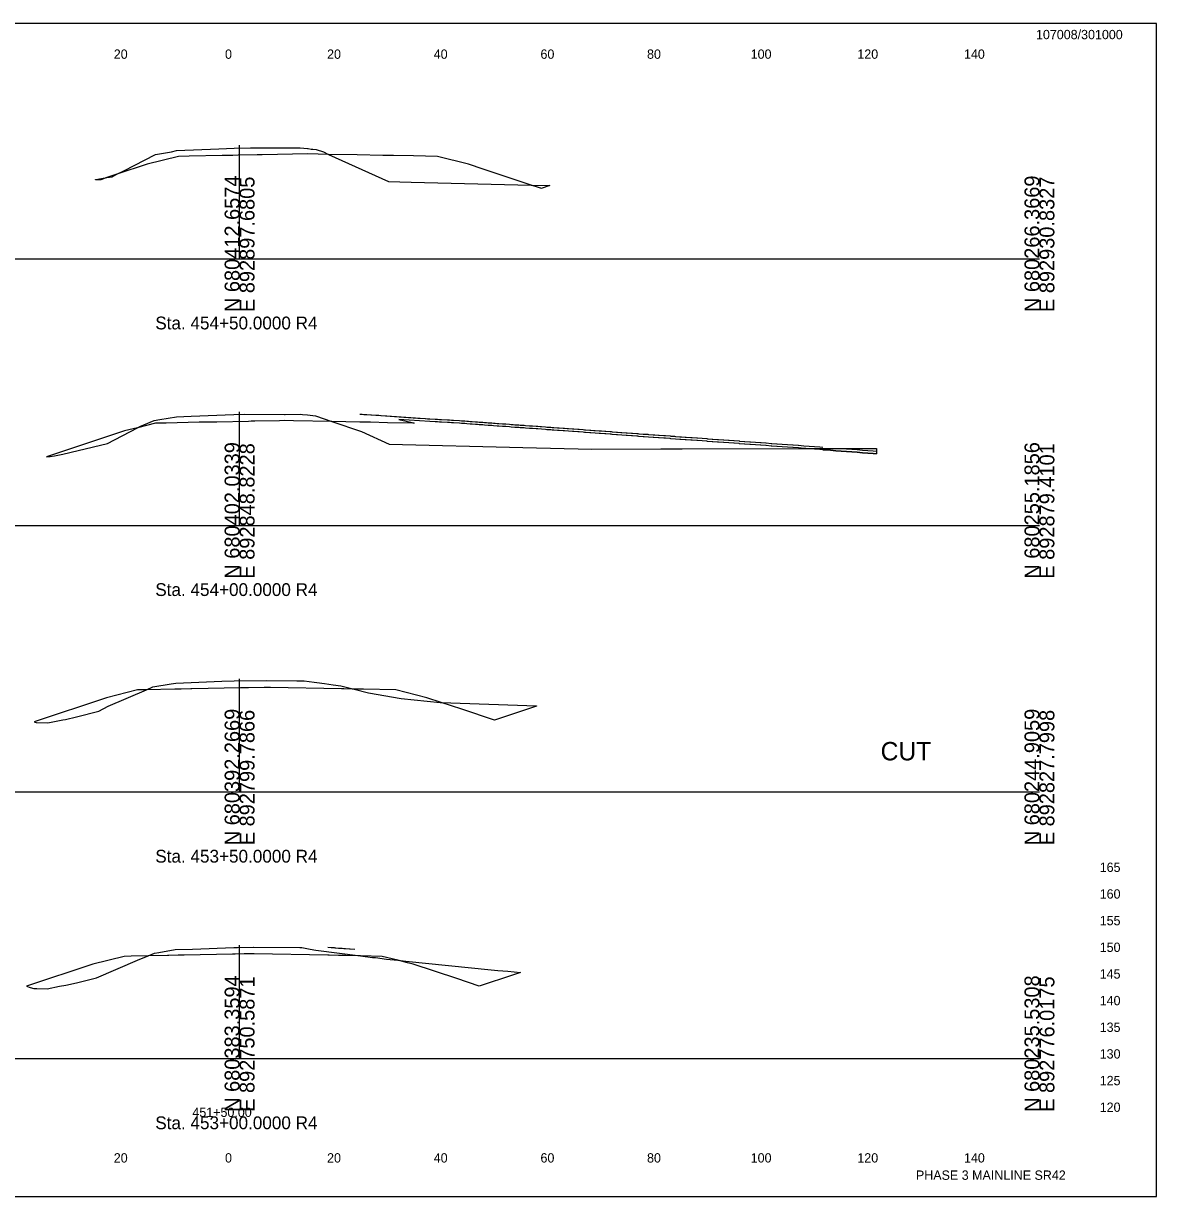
# Model space of a CAD drawing. Extents: x 21059 to 22955, y 6470 to 17494.
# Drawn here: x 21604.3 to 21816.8, y 7159 to 7379 of the extents above; entities that cross this region are included whole.
import ezdxf

# ---------------------------------------------------------------- set-up
doc = ezdxf.new("R2010")
doc.units = 0
for name, color, linetype in [('CONST_DCH', 7, 'Continuous'), ('Draft_XS_Grid', 7, 'Continuous'), ('Draft_XS_Text', 7, 'Continuous'), ('DTM CONTOURS_MAJOR', 7, 'Continuous'), ('DTM_TEMP_DROP', 7, 'Continuous'), ('SLOPE_STAKES_FILL', 7, 'Continuous'), ('X_PROFILES_1', 7, 'Continuous'), ('XS_M_SHAPES_EARTHWORK', 7, 'Continuous'), ('XS_P_TX_CLEARZONE', 7, 'Continuous'), ('XS_SHEET_EW_TX_VOLUME', 7, 'Continuous'), ('XS_X_SHOULDER', 7, 'Continuous')]:
    doc.layers.add(name, color=color, linetype=linetype)

msp = doc.modelspace()

# ---------------------------------------------------------------- linework, layer by layer
at = {"layer": 'DTM CONTOURS_MAJOR'}
for p, q in [((21644.84, 7334.84), (21644.84, 7356.12)), ((21494.84, 7334.84), (21644.84, 7334.84)), ((21644.84, 7334.84), (21794.84, 7334.84)), ((21644.84, 7284.84), (21644.84, 7306.1)), ((21494.84, 7284.84), (21644.84, 7284.84)), ((21644.84, 7284.84), (21794.84, 7284.84)), ((21644.84, 7234.84), (21644.84, 7256.08)), ((21494.84, 7234.84), (21644.84, 7234.84)), ((21644.84, 7234.84), (21794.84, 7234.84)), ((21644.84, 7184.84), (21644.84, 7206.12)), ((21494.84, 7184.84), (21644.84, 7184.84)), ((21644.84, 7184.84), (21794.84, 7184.84))]:
    msp.add_line(p, q, dxfattribs=at)
at = {"layer": 'DTM_TEMP_DROP'}
msp.add_lwpolyline([(21470.8, 7158.96), (21816.8, 7158.96), (21816.8, 7378.96), (21470.8, 7378.96)], close=True, dxfattribs=at)
at = {"layer": 'XS_M_SHAPES_EARTHWORK'}
for points in [[(21667.38, 7305.7), (21668.13, 7305.64), (21668.48, 7305.61), (21671.4, 7305.43)], [(21670.55, 7305.57), (21670.56, 7305.57), (21670.57, 7305.57), (21670.61, 7305.57), (21671.4, 7305.43), (21672.31, 7305.37), (21672.44, 7305.37), (21680.52, 7304.82), (21681.54, 7304.74), (21681.94, 7304.73), (21682.33, 7304.71), (21682.72, 7304.69), (21683.84, 7304.62), (21684.21, 7304.6), (21684.58, 7304.58), (21684.94, 7304.55), (21686.09, 7304.48), (21686.44, 7304.45), (21687.1, 7304.41), (21687.44, 7304.38), (21688.11, 7304.33), (21688.45, 7304.31), (21689.11, 7304.26), (21689.45, 7304.24), (21689.78, 7304.21), (21690.45, 7304.16), (21690.78, 7304.14), (21691.46, 7304.09), (21692.14, 7304.04), (21692.46, 7304.02), (21693.15, 7303.97), (21693.46, 7303.94), (21694.16, 7303.89), (21694.46, 7303.87), (21694.77, 7303.85), (21695.47, 7303.8), (21695.77, 7303.77), (21696.47, 7303.72), (21697.18, 7303.67), (21697.47, 7303.65), (21698.19, 7303.6), (21698.48, 7303.58), (21699.2, 7303.52), (21699.48, 7303.5), (21699.76, 7303.48), (21700.48, 7303.43), (21700.76, 7303.41), (21701.49, 7303.36), (21702.22, 7303.3), (21702.49, 7303.28), (21703.23, 7303.23), (21703.49, 7303.21), (21703.75, 7303.19), (21704.49, 7303.14), (21704.75, 7303.12), (21705.5, 7303.07), (21705.75, 7303.05), (21706.5, 7302.99), (21707.26, 7302.94), (21707.5, 7302.92), (21708.27, 7302.86), (21708.51, 7302.85), (21709.28, 7302.79), (21709.51, 7302.77), (21709.74, 7302.76), (21710.51, 7302.7), (21710.74, 7302.68), (21711.51, 7302.63), (21712.3, 7302.57), (21712.52, 7302.55), (21713.31, 7302.5), (21713.52, 7302.48), (21714.32, 7302.42), (21714.52, 7302.41), (21714.73, 7302.39), (21715.53, 7302.33), (21715.73, 7302.32), (21716.53, 7302.26), (21717.34, 7302.2), (21717.53, 7302.19), (21718.35, 7302.13), (21718.54, 7302.12), (21719.36, 7302.06), (21719.54, 7302.04), (21719.72, 7302.03), (21720.54, 7301.97), (21720.71, 7301.96), (21721.54, 7301.9), (21722.38, 7301.84), (21722.55, 7301.82), (21723.39, 7301.76), (21723.55, 7301.75), (21724.4, 7301.69), (21724.55, 7301.68), (21724.71, 7301.67), (21725.56, 7301.6), (21725.7, 7301.59), (21726.56, 7301.53), (21727.42, 7301.47), (21727.56, 7301.46), (21728.43, 7301.39), (21728.57, 7301.38), (21729.44, 7301.32), (21729.57, 7301.31), (21729.69, 7301.3), (21730.57, 7301.24), (21730.69, 7301.23), (21731.57, 7301.17), (21732.47, 7301.1), (21732.58, 7301.09), (21733.47, 7301.03), (21733.58, 7301.02), (21734.48, 7300.95), (21734.58, 7300.95), (21734.68, 7300.94), (21735.59, 7300.87), (21735.68, 7300.87), (21736.59, 7300.8), (21737.51, 7300.73), (21737.59, 7300.73), (21738.51, 7300.66), (21738.6, 7300.65), (21739.52, 7300.59), (21739.6, 7300.58), (21740.53, 7300.51), (21740.6, 7300.51), (21740.67, 7300.5), (21741.6, 7300.43), (21742.55, 7300.37), (21742.61, 7300.36), (21743.56, 7300.29), (21743.61, 7300.29), (21744.56, 7300.22), (21744.61, 7300.22), (21744.66, 7300.21), (21745.62, 7300.14), (21745.66, 7300.14), (21746.62, 7300.07), (21747.59, 7300), (21747.62, 7300), (21748.6, 7299.92), (21748.63, 7299.92), (21748.65, 7299.92), (21749.63, 7299.85), (21749.65, 7299.85), (21750.63, 7299.78), (21750.65, 7299.78), (21751.63, 7299.7), (21752.63, 7299.63), (21752.64, 7299.63), (21753.64, 7299.56), (21753.64, 7299.56), (21754.22, 7299.52)], [(21661.38, 7205.72), (21662, 7205.67), (21662.75, 7205.62)], [(21662.02, 7205.69), (21662.04, 7205.69), (21662.06, 7205.69), (21662.18, 7205.68), (21662.2, 7205.68), (21662.3, 7205.68), (21662.41, 7205.67), (21662.46, 7205.65), (21662.57, 7205.64), (21662.6, 7205.64), (21662.69, 7205.63), (21662.75, 7205.62), (21663.38, 7205.57), (21663.39, 7205.57), (21663.98, 7205.53), (21664.07, 7205.53), (21664.4, 7205.51), (21666.45, 7205.35)]]:
    msp.add_lwpolyline(points, dxfattribs=at)
at = {"layer": 'XS_P_TX_CLEARZONE'}
for points in [[(21667.38, 7305.7), (21667.79, 7305.68), (21667.84, 7305.68), (21678.27, 7304.94), (21678.72, 7304.92), (21679.68, 7304.85), (21680.1, 7304.83), (21680.52, 7304.82), (21681.54, 7304.74), (21681.94, 7304.73), (21682.33, 7304.71), (21682.72, 7304.69), (21683.84, 7304.62), (21684.21, 7304.6), (21684.58, 7304.58), (21684.94, 7304.55), (21686.09, 7304.48), (21686.44, 7304.45), (21686.79, 7304.43), (21687.44, 7304.38), (21687.79, 7304.36), (21688.45, 7304.31), (21689.11, 7304.26), (21689.45, 7304.24), (21689.78, 7304.21), (21690.45, 7304.16), (21691.13, 7304.11), (21691.46, 7304.09), (21692.14, 7304.04), (21692.46, 7304.02), (21692.77, 7303.99), (21693.46, 7303.94), (21694.16, 7303.89), (21694.46, 7303.87), (21694.77, 7303.85), (21695.47, 7303.8), (21696.17, 7303.75), (21696.47, 7303.72), (21697.18, 7303.67), (21697.47, 7303.65), (21698.19, 7303.6), (21698.48, 7303.58), (21699.2, 7303.52), (21699.48, 7303.5), (21699.76, 7303.48), (21700.48, 7303.43), (21701.21, 7303.38), (21701.49, 7303.36), (21702.22, 7303.3), (21702.49, 7303.28), (21702.75, 7303.27), (21703.49, 7303.21), (21703.75, 7303.19), (21704.49, 7303.14), (21704.75, 7303.12), (21705.5, 7303.07), (21706.25, 7303.01), (21706.5, 7302.99), (21707.26, 7302.94), (21707.5, 7302.92), (21708.27, 7302.86), (21708.51, 7302.85), (21709.28, 7302.79), (21709.51, 7302.77), (21709.74, 7302.76), (21710.51, 7302.7), (21711.29, 7302.64), (21711.51, 7302.63), (21712.3, 7302.57), (21712.52, 7302.55), (21712.73, 7302.54), (21713.52, 7302.48), (21714.32, 7302.42), (21714.52, 7302.41), (21714.73, 7302.39), (21715.53, 7302.33), (21716.33, 7302.28), (21716.53, 7302.26), (21717.34, 7302.2), (21717.53, 7302.19), (21718.35, 7302.13), (21718.54, 7302.12), (21719.36, 7302.06), (21719.54, 7302.04), (21719.72, 7302.03), (21720.54, 7301.97), (21721.38, 7301.91), (21721.54, 7301.9), (21722.38, 7301.84), (21722.55, 7301.82), (21722.71, 7301.81), (21723.55, 7301.75), (21724.4, 7301.69), (21724.55, 7301.68), (21724.71, 7301.67), (21725.56, 7301.6), (21726.42, 7301.54), (21726.56, 7301.53), (21727.42, 7301.47), (21727.56, 7301.46), (21727.7, 7301.45), (21728.57, 7301.38), (21729.44, 7301.32), (21729.57, 7301.31), (21729.69, 7301.3), (21730.57, 7301.24), (21730.69, 7301.23), (21731.57, 7301.17), (21732.47, 7301.1), (21732.58, 7301.09), (21732.69, 7301.08), (21733.58, 7301.02), (21734.48, 7300.95), (21734.58, 7300.95), (21734.68, 7300.94), (21735.59, 7300.87), (21736.5, 7300.81), (21736.59, 7300.8), (21736.68, 7300.79), (21737.59, 7300.73), (21738.51, 7300.66), (21738.6, 7300.65), (21739.52, 7300.59), (21739.6, 7300.58), (21740.53, 7300.51), (21740.6, 7300.51), (21740.67, 7300.5), (21741.6, 7300.43), (21742.55, 7300.37), (21742.61, 7300.36), (21742.67, 7300.36), (21743.61, 7300.29), (21744.56, 7300.22), (21744.61, 7300.22), (21744.66, 7300.21), (21745.62, 7300.14), (21745.66, 7300.14), (21746.62, 7300.07), (21747.59, 7300), (21747.62, 7300), (21748.6, 7299.92), (21748.63, 7299.92), (21749.6, 7299.85), (21749.63, 7299.85), (21749.65, 7299.85), (21750.63, 7299.78), (21750.65, 7299.78), (21751.63, 7299.7), (21752.63, 7299.63), (21752.64, 7299.63), (21752.64, 7299.63), (21753.64, 7299.56), (21754.22, 7299.52)], [(21661.38, 7205.72), (21662, 7205.67), (21666.45, 7205.35)]]:
    msp.add_lwpolyline(points, dxfattribs=at)
at = {"layer": 'XS_SHEET_EW_TX_VOLUME'}
for points in [[(21621.83, 7350.67), (21623.14, 7351.33), (21629.06, 7354.42), (21632.1, 7354.89), (21633, 7355.11), (21640.97, 7355.48), (21643.8, 7355.6), (21646.86, 7355.63), (21656.16, 7355.66), (21656.19, 7355.62), (21657.55, 7355.51), (21657.73, 7355.49), (21658.26, 7355.42), (21658.57, 7355.41), (21659.23, 7355.32), (21660.59, 7354.86), (21661.54, 7354.42), (21657.66, 7354.5), (21649.1, 7354.33), (21648.75, 7354.32), (21648.14, 7354.31), (21644.55, 7354.24), (21643.6, 7354.22), (21641.83, 7354.19), (21641.59, 7354.18), (21635.36, 7354.06), (21633.38, 7354.02), (21627.53, 7352.56)], [(21661.54, 7354.42), (21672.74, 7349.31), (21677.02, 7349.21), (21699.53, 7348.66), (21690.55, 7351.65), (21687.79, 7352.56), (21681.94, 7354.02), (21677.46, 7354.11), (21673.73, 7354.18), (21672.82, 7354.2), (21671.72, 7354.22), (21666.91, 7354.32)], [(21619.95, 7350.05), (21620.94, 7350.22), (21621.83, 7350.67)], [(21617.85, 7349.64), (21617.85, 7349.67), (21617.88, 7349.68), (21619.95, 7350.05), (21618.8, 7349.66), (21618.41, 7349.65)], [(21699.53, 7348.66), (21703.05, 7348.58), (21701.42, 7348.04), (21701.35, 7348.06), (21701.09, 7348.15)], [(21625.71, 7303.15), (21626.11, 7303.36), (21628.81, 7304.51), (21629.91, 7304.7), (21632.98, 7305.18), (21635.79, 7305.3), (21643.78, 7305.66), (21645.79, 7305.67), (21653.24, 7305.65), (21653.36, 7305.65), (21656.33, 7305.68), (21656.61, 7305.66), (21657.57, 7305.56), (21659.05, 7305.36), (21662.16, 7304.3), (21654.95, 7304.45), (21653.34, 7304.48), (21652.32, 7304.46), (21647.67, 7304.36), (21647.02, 7304.35), (21646.49, 7304.34), (21640.58, 7304.22), (21639.3, 7304.2), (21637.57, 7304.16), (21637.29, 7304.16), (21631.05, 7304.03), (21629.1, 7303.99)], [(21662.16, 7304.3), (21667.71, 7302.42), (21672.89, 7300.06), (21697.93, 7299.44), (21710.93, 7299.13), (21723.85, 7299.21), (21727.83, 7299.2), (21750.08, 7299.25), (21751.01, 7299.25), (21750.65, 7299.28), (21750.63, 7299.28), (21749.65, 7299.35), (21749.63, 7299.35), (21748.65, 7299.42), (21748.63, 7299.42), (21748.6, 7299.42), (21747.62, 7299.5), (21747.59, 7299.5), (21746.62, 7299.57), (21745.66, 7299.64), (21745.62, 7299.64), (21744.66, 7299.71), (21744.61, 7299.72), (21744.56, 7299.72), (21743.61, 7299.79), (21743.56, 7299.79), (21742.61, 7299.86), (21742.55, 7299.87), (21741.6, 7299.93), (21740.67, 7300), (21740.6, 7300.01), (21740.53, 7300.01), (21739.6, 7300.08), (21739.52, 7300.09), (21738.6, 7300.15), (21738.51, 7300.16), (21737.59, 7300.23), (21737.51, 7300.23), (21736.59, 7300.3), (21735.68, 7300.37), (21735.59, 7300.37), (21734.68, 7300.44), (21734.58, 7300.45), (21734.48, 7300.45), (21733.58, 7300.52), (21733.47, 7300.53), (21732.58, 7300.59), (21732.47, 7300.6), (21731.57, 7300.67), (21730.69, 7300.73), (21730.57, 7300.74), (21729.69, 7300.8), (21729.57, 7300.81), (21729.44, 7300.82), (21728.57, 7300.88), (21728.43, 7300.89), (21727.56, 7300.96), (21727.42, 7300.97), (21726.56, 7301.03), (21725.7, 7301.09), (21725.56, 7301.1), (21724.71, 7301.17), (21724.55, 7301.18), (21724.4, 7301.19), (21723.55, 7301.25), (21723.39, 7301.26), (21722.55, 7301.32), (21722.38, 7301.34), (21721.54, 7301.4), (21720.71, 7301.46), (21720.54, 7301.47), (21719.72, 7301.53), (21719.54, 7301.54), (21719.36, 7301.56), (21718.54, 7301.62), (21718.35, 7301.63), (21717.53, 7301.69), (21717.34, 7301.7), (21716.53, 7301.76), (21715.73, 7301.82), (21715.53, 7301.83), (21714.73, 7301.89), (21714.52, 7301.91), (21714.32, 7301.92), (21713.52, 7301.98), (21713.31, 7302), (21712.52, 7302.05), (21712.3, 7302.07), (21711.51, 7302.13), (21710.74, 7302.18), (21710.51, 7302.2), (21709.74, 7302.26), (21709.51, 7302.27), (21709.28, 7302.29), (21708.51, 7302.35), (21708.27, 7302.36), (21707.5, 7302.42), (21707.26, 7302.44), (21706.5, 7302.49), (21705.75, 7302.55), (21705.5, 7302.57), (21704.75, 7302.62), (21704.49, 7302.64), (21703.75, 7302.69), (21703.49, 7302.71), (21703.23, 7302.73), (21702.49, 7302.78), (21702.22, 7302.8), (21701.49, 7302.86), (21700.76, 7302.91), (21700.48, 7302.93), (21699.76, 7302.98), (21699.48, 7303), (21699.2, 7303.02), (21698.48, 7303.08), (21698.19, 7303.1), (21697.47, 7303.15), (21697.18, 7303.17), (21696.47, 7303.22), (21695.77, 7303.27), (21695.47, 7303.3), (21694.77, 7303.35), (21694.46, 7303.37), (21694.16, 7303.39), (21693.46, 7303.44), (21693.15, 7303.47), (21692.46, 7303.52), (21692.14, 7303.54), (21691.46, 7303.59), (21690.78, 7303.64), (21690.45, 7303.66), (21689.78, 7303.71), (21689.45, 7303.74), (21689.11, 7303.76), (21688.45, 7303.81), (21688.11, 7303.83), (21687.44, 7303.88), (21687.1, 7303.91), (21686.44, 7303.95), (21686.09, 7303.98), (21684.94, 7304.05), (21684.58, 7304.08), (21684.21, 7304.1), (21683.84, 7304.12), (21682.72, 7304.19), (21682.33, 7304.21), (21681.94, 7304.23), (21681.54, 7304.24), (21680.52, 7304.32), (21674.71, 7304.71), (21676.92, 7304.16), (21677.59, 7304), (21672.59, 7304.09), (21669.39, 7304.16), (21668.02, 7304.19), (21667.38, 7304.2)], [(21608.63, 7297.68), (21609.33, 7297.73), (21610.16, 7297.9), (21611.69, 7298.18), (21618.73, 7299.86), (21620.08, 7300.21), (21625.71, 7303.15), (21623.25, 7302.54)], [(21751.01, 7299.25), (21764.29, 7299.28), (21764.29, 7298.28), (21763.67, 7298.33), (21762.67, 7298.4), (21761.66, 7298.47), (21760.66, 7298.55), (21759.66, 7298.62), (21758.65, 7298.69), (21757.65, 7298.77), (21756.65, 7298.84), (21755.65, 7298.91), (21754.64, 7298.98), (21754.22, 7299.02), (21753.64, 7299.06), (21753.64, 7299.06), (21752.64, 7299.13), (21752.63, 7299.13), (21751.63, 7299.2)], [(21757.68, 7299.27), (21764.29, 7299.28), (21764.29, 7298.68), (21763.67, 7298.73), (21762.67, 7298.82), (21761.66, 7298.9), (21760.66, 7298.98), (21759.66, 7299.07), (21758.65, 7299.15), (21757.69, 7299.22)], [(21627.38, 7254.01), (21628.59, 7254.53), (21631.98, 7255.11), (21632.89, 7255.25), (21641.49, 7255.61), (21643.83, 7255.71), (21649.9, 7255.75), (21649.91, 7255.75), (21655.58, 7255.69), (21656.47, 7255.7), (21656.97, 7255.66), (21658.8, 7255.44), (21659.32, 7255.35), (21660.79, 7255.16), (21662.37, 7254.96), (21663.84, 7254.77), (21666.32, 7254.13), (21665.94, 7254.14), (21664.37, 7254.17), (21663.94, 7254.18), (21650.61, 7254.45), (21649.91, 7254.46), (21649.42, 7254.45), (21646.53, 7254.39), (21646.11, 7254.38), (21645, 7254.36), (21635.89, 7254.18), (21635.67, 7254.18), (21633.88, 7254.14), (21632.68, 7254.12)], [(21606.3, 7248.01), (21606.69, 7247.86), (21608.78, 7247.81), (21609.19, 7247.84), (21611.72, 7248.35), (21612.18, 7248.44), (21614.27, 7248.94), (21618.42, 7250.01), (21620.19, 7250.94), (21627.38, 7254.01), (21625.7, 7253.98), (21619.86, 7252.52)], [(21666.32, 7254.13), (21668.99, 7253.45), (21675.14, 7252.36), (21682.43, 7251.63), (21682.67, 7251.62), (21679.97, 7252.52), (21674.13, 7253.98), (21668.08, 7254.1)], [(21682.67, 7251.62), (21700.5, 7251), (21700.5, 7250.9), (21692.67, 7248.29), (21686.5, 7250.35)], [(21627.7, 7204.1), (21628.87, 7204.58), (21629.67, 7204.74), (21632.75, 7205.27), (21636.01, 7205.38), (21643.78, 7205.7), (21644.44, 7205.7), (21647.37, 7205.71), (21647.43, 7205.71), (21656.16, 7205.69), (21656.53, 7205.66), (21658.05, 7205.36), (21659.12, 7205.16), (21667.54, 7204.09), (21664.71, 7204.15), (21663.38, 7204.18), (21661.65, 7204.21), (21661.38, 7204.22), (21647.6, 7204.49), (21647.37, 7204.5), (21647.19, 7204.49), (21645.68, 7204.46), (21644.04, 7204.43), (21643.53, 7204.42), (21634.43, 7204.24), (21633.35, 7204.22), (21631.55, 7204.18), (21631.35, 7204.18)], [(21604.89, 7198.41), (21605.59, 7198.14), (21606.24, 7197.97), (21606.83, 7197.98), (21608.73, 7197.94), (21611.05, 7198.4), (21612.27, 7198.61), (21614.25, 7199.02), (21618.03, 7200.01), (21625.68, 7203.28), (21627.7, 7204.1), (21624.48, 7204.04), (21623.17, 7204.01), (21617.34, 7202.56)], [(21667.54, 7204.09), (21669.78, 7203.81), (21670.33, 7203.78), (21672.4, 7203.51), (21674.53, 7203.27), (21671.56, 7204.01)], [(21674.53, 7203.27), (21676.03, 7203.1), (21692.04, 7201.47), (21693.25, 7201.36), (21695.13, 7201.21), (21697.54, 7201.01), (21697.54, 7201), (21696.24, 7200.56), (21689.8, 7198.42), (21685.56, 7199.84), (21677.39, 7202.56), (21676.33, 7202.82)]]:
    msp.add_lwpolyline(points, close=True, dxfattribs=at)
at = {"layer": 'XS_X_SHOULDER'}
msp.add_lwpolyline([(21754.22, 7299.02), (21754.64, 7298.98), (21755.65, 7298.91), (21756.65, 7298.84), (21757.65, 7298.77), (21758.65, 7298.69), (21759.66, 7298.62), (21760.66, 7298.55), (21761.66, 7298.47), (21762.67, 7298.4), (21763.67, 7298.33), (21764.29, 7298.28)], dxfattribs=at)

# ---------------------------------------------------------------- texts
at = {"layer": 'CONST_DCH'}
for p in [(21618.76, 7349.6), (21618.76, 7349.6), (21701.38, 7347.98), (21701.38, 7347.98), (21608.59, 7297.62), (21608.59, 7297.62), (21696.55, 7298.11), (21696.55, 7298.11), (21606.26, 7247.95), (21606.26, 7247.95), (21692.63, 7248.23), (21692.63, 7248.23), (21604.85, 7198.35), (21604.85, 7198.35), (21689.77, 7198.36), (21689.77, 7198.36)]:
    msp.add_text('X', height=0.12, dxfattribs=at).set_placement(p)
at = {"layer": 'Draft_XS_Grid'}
for s, p in [('  165  ', (21804.84, 7219.84)), ('  160  ', (21804.84, 7214.84)), ('  155  ', (21804.84, 7209.84)), ('  150  ', (21804.84, 7204.84)), ('  145  ', (21804.84, 7199.84)), ('  140  ', (21804.84, 7194.84)), ('  135  ', (21804.84, 7189.84)), ('  130  ', (21804.84, 7184.84)), ('  125  ', (21804.84, 7179.84)), ('  120  ', (21804.84, 7174.84))]:
    msp.add_text(s, height=1.75, dxfattribs=at).set_placement(p)
at = {"layer": 'Draft_XS_Text'}
for s, height, p in [('107008/301000', 1.75, (21794.19, 7376.01)), ('  20  ', 1.75, (21619.95, 7372.34)), ('  0  ', 1.75, (21640.81, 7372.34)), ('  0  ', 1.75, (21640.81, 7372.34)), ('  20  ', 1.75, (21659.95, 7372.34)), ('  40  ', 1.75, (21679.95, 7372.34)), ('  60  ', 1.75, (21699.97, 7372.34)), ('  80  ', 1.75, (21719.95, 7372.34)), ('  100  ', 1.75, (21739.39, 7372.34)), ('  120  ', 1.75, (21759.39, 7372.34)), ('  140  ', 1.75, (21779.39, 7372.34)), ('CUT', 3.455, (21765.06, 7240.76)), ('  20  ', 1.75, (21619.95, 7165.34)), ('  0  ', 1.75, (21640.81, 7165.34)), ('  0  ', 1.75, (21640.81, 7165.34)), ('  20  ', 1.75, (21659.95, 7165.34)), ('  40  ', 1.75, (21679.95, 7165.34)), ('  60  ', 1.75, (21699.97, 7165.34)), ('  80  ', 1.75, (21719.95, 7165.34)), ('  100  ', 1.75, (21739.39, 7165.34)), ('  120  ', 1.75, (21759.39, 7165.34)), ('  140  ', 1.75, (21779.39, 7165.34)), ('PHASE 3 MAINLINE SR42', 1.75, (21771.68, 7162.1))]:
    msp.add_text(s, height=height, dxfattribs=at).set_placement(p)
at = {"layer": 'DTM CONTOURS_MAJOR'}
for s, p in [('N 680412.6574', (21644.84, 7324.84)), ('N 680266.3669', (21794.84, 7324.84)), ('E 892897.6805', (21647.64, 7324.84)), ('E 892930.8327', (21797.64, 7324.84)), ('N 680402.0339', (21644.84, 7274.84)), ('E 892848.8228', (21647.64, 7274.84)), ('N 680255.1856', (21794.84, 7274.84)), ('E 892879.4101', (21797.64, 7274.84)), ('N 680392.2669', (21644.84, 7224.84)), ('E 892799.7866', (21647.64, 7224.84)), ('N 680244.9059', (21794.84, 7224.84)), ('E 892827.7998', (21797.64, 7224.84)), ('N 680383.3594', (21644.84, 7174.84)), ('E 892750.5871', (21647.64, 7174.84)), ('N 680235.5308', (21794.84, 7174.84)), ('E 892776.0175', (21797.64, 7174.84))]:
    msp.add_text(s, height=2.8, rotation=90, dxfattribs=at).set_placement(p)
at = {"layer": 'SLOPE_STAKES_FILL'}
msp.add_text('  451+50.00  ', height=1.75, dxfattribs=at).set_placement((21634.69, 7173.89))
at = {"layer": 'X_PROFILES_1'}
for s, p in [('Sta. 454+50.0000 R4', (21629.03, 7321.59)), ('Sta. 454+00.0000 R4', (21629.03, 7271.59)), ('Sta. 453+50.0000 R4', (21629.03, 7221.59)), ('Sta. 453+00.0000 R4', (21629.03, 7171.59))]:
    msp.add_text(s, height=2.4, dxfattribs=at).set_placement(p)

doc.saveas('drawing.dxf')
